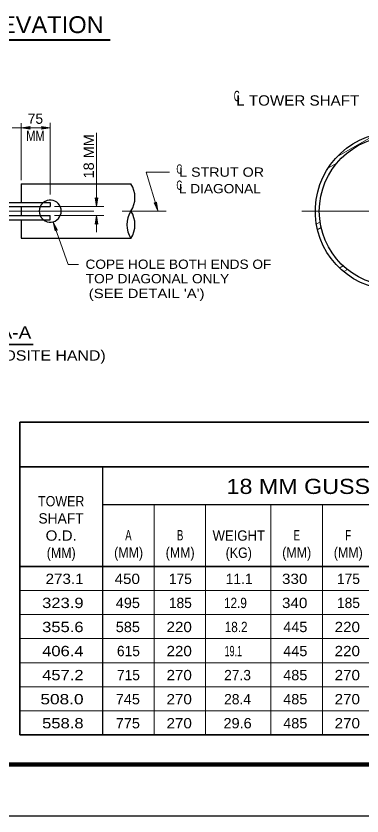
# Model space of a CAD drawing. Extents: x 312601.858 to 312602.699, y 144420.109 to 144420.704.
# Drawn here: x 312602.0136 to 312602.1142, y 144420.1095 to 144420.3423 of the extents above; entities that cross this region are included whole.
import ezdxf
from ezdxf.enums import TextEntityAlignment as Align

# ---------------------------------------------------------------- set-up
doc = ezdxf.new("R2010")
doc.units = 0
doc.header["$LTSCALE"] = 0.0012
doc.linetypes.add('DOT_DASHED', pattern=[7.7, 5, -1.2, 0.3, -1.2])
doc.linetypes.add('DOTTED', pattern=[1.5, 0.3, -1.2])
for name, color, linetype, lineweight in [('1', 7, 'Continuous', 25), ('2', 7, 'Continuous', 13), ('39', 7, 'Continuous', 13)]:
    doc.layers.add(name, color=color, linetype=linetype, lineweight=lineweight)

msp = doc.modelspace()

# ---------------------------------------------------------------- hatches: boundary and pattern name
at = {"layer": '39'}
for points in [[(312602.0174, 144420.3097), (312602.0177, 144420.3093), (312602.0151, 144420.3097), (312602.0177, 144420.3101)], [(312602.0174, 144420.3097), (312602.0177, 144420.3093), (312602.0151, 144420.3097), (312602.0177, 144420.3101)], [(312602.0212, 144420.3097), (312602.021, 144420.3101), (312602.0235, 144420.3097), (312602.021, 144420.3093)], [(312602.0212, 144420.3097), (312602.021, 144420.3101), (312602.0235, 144420.3097), (312602.021, 144420.3093)], [(312602.037, 144420.2891), (312602.0374, 144420.2894), (312602.037, 144420.2868), (312602.0366, 144420.2894)], [(312602.0541, 144420.2878), (312602.0544, 144420.2881), (312602.0548, 144420.2856), (312602.0537, 144420.2879)], [(312602.037, 144420.2819), (312602.0366, 144420.2817), (312602.037, 144420.2842), (312602.0374, 144420.2817)], [(312602.0252, 144420.2801), (312602.0249, 144420.2798), (312602.0244, 144420.2823), (312602.0256, 144420.28)]]:
    msp.add_hatch(color=256, dxfattribs=at).paths.add_polyline_path(points)

# ---------------------------------------------------------------- linework, layer by layer
at = {"layer": '1', "lineweight": 13}
for p, q in [((312602.0151, 144420.3111), (312602.0151, 144420.2945)), ((312602.0235, 144420.3112), (312602.0235, 144420.2903)), ((312602.037, 144420.3083), (312602.037, 144420.2868)), ((312602.1069, 144420.3013), (312602.1182, 144420.3078)), ((312602.1043, 144420.298), (312602.1069, 144420.2995)), ((312602.0514, 144420.2968), (312602.0582, 144420.2968)), ((312602.0514, 144420.2968), (312602.0548, 144420.2856)), ((312602.0247, 144420.2868), (312602.0391, 144420.2868)), ((312602.0247, 144420.2842), (312602.0391, 144420.2842)), ((312602.037, 144420.2842), (312602.037, 144420.2794)), ((312602.0444, 144420.2855), (312602.0572, 144420.2855)), ((312602.1009, 144420.2817), (312602.1021, 144420.2824)), ((312602.1012, 144420.2801), (312602.1023, 144420.2807)), ((312602.1076, 144420.2689), (312602.1087, 144420.2696)), ((312602.1089, 144420.2679), (312602.11, 144420.2685))]:
    msp.add_line(p, q, dxfattribs=at)
at = {"layer": '1'}
for p, q in [((312602.0151, 144420.2934), (312602.047, 144420.2934)), ((312602.0151, 144420.2934), (312602.0151, 144420.288)), ((312601.986, 144420.2868), (312602.0235, 144420.2868)), ((312601.9884, 144420.288), (312602.0235, 144420.288)), ((312602.0151, 144420.2868), (312602.0151, 144420.2842)), ((312602.0235, 144420.288), (312602.0235, 144420.2868)), ((312601.986, 144420.2842), (312602.0235, 144420.2842))]:
    msp.add_line(p, q, dxfattribs=at)
at = {"layer": '1', "linetype": 'DOT_DASHED', "lineweight": 13}
for p, q in [((312601.9362, 144420.2855), (312602.0468, 144420.2855)), ((312602.0967, 144420.2855), (312602.2188, 144420.2855))]:
    msp.add_line(p, q, dxfattribs=at)
at = {"layer": '1', "lineweight": 13}
for points in [[(312602.0124, 144420.3097), (312602.0151, 144420.3097), (312602.0235, 144420.3097)], [(312602.0317, 144420.27), (312602.0287, 144420.27), (312602.0244, 144420.2823)]]:
    msp.add_lwpolyline(points, dxfattribs=at)
at = {"layer": '1'}
for points in [[(312601.9884, 144420.283), (312602.0235, 144420.283), (312602.0235, 144420.2842)], [(312602.0151, 144420.283), (312602.0151, 144420.2776), (312602.047, 144420.2776)]]:
    msp.add_lwpolyline(points, dxfattribs=at)
msp.add_circle((312602.12356, 144420.2855), 0.02178, dxfattribs=at)
for centre, radius, start, end in [((312602.12356, 144420.2855), 0.02295, 3.25763, 2.95461), ((312602.0235, 144420.2855), 0.0032, 232.26694, 128.41806), ((312602.0235, 144420.2855), 0.0032, 156.57131, 203.32061)]:
    msp.add_arc(centre, radius, start, end, dxfattribs=at)
at = {"layer": '1', "linetype": 'DOTTED'}
for start, end in [(129.55967, 155.09523), (204.90477, 228.99091)]:
    msp.add_arc((312602.0235, 144420.2855), 0.0032, start, end, dxfattribs=at)
at = {"layer": '2', "lineweight": 40}
msp.add_line((312601.972, 144420.3353), (312602.0409, 144420.3353), dxfattribs=at)
at = {"layer": '2', "lineweight": 35}
for p, q in [((312601.982, 144420.2467), (312602.0185, 144420.2467)), ((312602.0147, 144420.2241), (312602.0147, 144420.1331)), ((312602.0147, 144420.2241), (312602.3284, 144420.2241)), ((312602.0147, 144420.2111), (312602.3287, 144420.2111)), ((312602.0147, 144420.1821), (312602.3287, 144420.1821)), ((312602.0147, 144420.1331), (312602.3287, 144420.1331))]:
    msp.add_line(p, q, dxfattribs=at)
at = {"layer": '2'}
for p, q in [((312602.0147, 144420.2241), (312602.0147, 144420.1331)), ((312602.0537, 144420.2001), (312602.0537, 144420.1331)), ((312602.0687, 144420.2001), (312602.0687, 144420.1331)), ((312602.0877, 144420.2001), (312602.0877, 144420.1331)), ((312602.1027, 144420.2001), (312602.1027, 144420.1331)), ((312602.0147, 144420.1751), (312602.3287, 144420.1751)), ((312602.0147, 144420.1681), (312602.3287, 144420.1681)), ((312602.0147, 144420.1611), (312602.3284, 144420.1611)), ((312602.0147, 144420.1541), (312602.3287, 144420.1541)), ((312602.0147, 144420.1471), (312602.3287, 144420.1471)), ((312602.0147, 144420.1401), (312602.3287, 144420.1401))]:
    msp.add_line(p, q, dxfattribs=at)
at = {"layer": '2', "lineweight": 25}
for p, q in [((312602.0387, 144420.2111), (312602.0387, 144420.1331)), ((312602.0387, 144420.2001), (312602.3287, 144420.2001))]:
    msp.add_line(p, q, dxfattribs=at)
for centre, start, end in [((312602.040877, 144420.28946), 327.02071, 32.97929), ((312602.053083, 144420.28154), 147.02071, 212.97929), ((312602.040877, 144420.28154), 327.02071, 32.97929)]:
    msp.add_arc(centre, 0.007275, start, end, dxfattribs=at)
at = {"layer": '39', "lineweight": 158}
msp.add_line((312601.9088, 144420.1245), (312602.6838, 144420.1245), dxfattribs=at)
at = {"layer": '39', "lineweight": 25}
msp.add_line((312601.8578, 144420.1095), (312602.6988, 144420.1095), dxfattribs=at)
at = {"layer": '39'}
for points in [[(312602.0174, 144420.3097), (312602.0177, 144420.3093), (312602.0151, 144420.3097), (312602.0177, 144420.3101)], [(312602.0174, 144420.3097), (312602.0177, 144420.3093), (312602.0151, 144420.3097), (312602.0177, 144420.3101)], [(312602.0212, 144420.3097), (312602.021, 144420.3101), (312602.0235, 144420.3097), (312602.021, 144420.3093)], [(312602.0212, 144420.3097), (312602.021, 144420.3101), (312602.0235, 144420.3097), (312602.021, 144420.3093)], [(312602.037, 144420.2891), (312602.0374, 144420.2894), (312602.037, 144420.2868), (312602.0366, 144420.2894)], [(312602.0541, 144420.2878), (312602.0544, 144420.2881), (312602.0548, 144420.2856), (312602.0537, 144420.2879)], [(312602.037, 144420.2819), (312602.0366, 144420.2817), (312602.037, 144420.2842), (312602.0374, 144420.2817)], [(312602.0252, 144420.2801), (312602.0249, 144420.2798), (312602.0244, 144420.2823), (312602.0256, 144420.28)]]:
    msp.add_lwpolyline(points, close=True, dxfattribs=at)

# ---------------------------------------------------------------- texts
at = {"layer": '2'}
for s, height, width, p in [('TOWER ELEVATION', 0.0049, 1.05, (312602.006, 144420.3373)), ('MM', 0.003, 0.8, (312602.0192, 144420.3059)), ('C', 0.0027, 0.65, (312602.06105, 144420.2964)), ('L STRUT OR', 0.0027, 1.15, (312602.07335, 144420.2955)), ('C', 0.0027, 0.65, (312602.06105, 144420.2917)), ('L DIAGONAL', 0.0027, 1.1, (312602.07285, 144420.2907)), ('COPE HOLE BOTH ENDS OF', 0.0027, 1.1, (312602.0608, 144420.2687)), ('TOP DIAGONAL ONLY', 0.0027, 1.1, (312602.0547, 144420.2645)), ("(SEE DETAIL 'A')", 0.0027, 1.2, (312602.05155, 144420.2602)), ('SECTION A-A', 0.0036, 1.15, (312602.0003, 144420.2484)), ('(SECTION D-D OPPOSITE HAND)', 0.003, 1.15, (312602.0035, 144420.242)), ('18 MM GUSSET PLATE', 0.0044, 1.15, (312602.11165, 144420.2032)), ('TOWER', 0.003, 0.9, (312602.0267, 144420.1996)), ('O.D.', 0.003, 1.1, (312602.0267, 144420.1896)), ('A', 0.003, 0.7, (312602.04625, 144420.1897)), ('B', 0.003, 0.7, (312602.0613, 144420.1897)), ('WEIGHT', 0.003, 0.95, (312602.07835, 144420.1896)), ('E', 0.003, 0.7, (312602.0952, 144420.1897)), ('F', 0.003, 0.7, (312602.11015, 144420.1897)), ('(MM)', 0.003, 0.9, (312602.0267, 144420.1846)), ('(MM)', 0.003, 0.9, (312602.0463, 144420.1847)), ('(MM)', 0.003, 0.9, (312602.0613, 144420.1847)), ('(KG)', 0.003, 0.9, (312602.07835, 144420.1846)), ('(MM)', 0.003, 0.9, (312602.0952, 144420.1847)), ('(MM)', 0.003, 0.9, (312602.1102, 144420.1847))]:
    msp.add_text(s, height=height, dxfattribs=dict(at, width=width)).set_placement(p, align=Align.CENTER)
for s, width, p in [('C', 0.6, (312602.0769, 144420.3175)), ('L TOWER SHAFT', 1.1, (312602.0776, 144420.3162))]:
    msp.add_text(s, height=0.003, dxfattribs=dict(at, width=width)).set_placement(p)
for s, p in [('75', (312602.0192, 144420.3109)), ('SHAFT', (312602.02665, 144420.1946))]:
    msp.add_text(s, height=0.003, dxfattribs=at).set_placement(p, align=Align.CENTER)
at = {"layer": '2', "width": 1.05}
msp.add_text('18 MM', height=0.003, rotation=90, dxfattribs=at).set_placement((312602.0362, 144420.30145), align=Align.CENTER)
at = {"layer": '2'}
for s, width, p in [('273.1', 1.1, (312602.0332, 144420.177)), ('450', 1.1, (312602.0496, 144420.177)), ('330', 1.1, (312602.0983, 144420.177)), ('323.9', 1.2, (312602.0332, 144420.17)), ('495', 1.05, (312602.0496, 144420.17)), ('12.9', 0.85, (312602.0807, 144420.17)), ('340', 1.1, (312602.0983, 144420.17)), ('355.6', 1.2, (312602.0332, 144420.163)), ('585', 1.05, (312602.0496, 144420.163)), ('220', 1.1, (312602.0647, 144420.163)), ('18.2', 0.85, (312602.0809, 144420.163)), ('445', 1.05, (312602.0983, 144420.163)), ('220', 1.1, (312602.1136, 144420.163)), ('406.4', 1.2, (312602.0332, 144420.156)), ('220', 1.1, (312602.0647, 144420.156)), ('19.1', 0.65, (312602.0793, 144420.156)), ('445', 1.05, (312602.0983, 144420.156)), ('220', 1.1, (312602.1136, 144420.156)), ('457.2', 1.2, (312602.0332, 144420.149)), ('270', 1.1, (312602.0647, 144420.149)), ('485', 1.05, (312602.0983, 144420.149)), ('270', 1.1, (312602.1136, 144420.149)), ('508.0', 1.25, (312602.0332, 144420.142)), ('745', 1.05, (312602.0496, 144420.142)), ('270', 1.1, (312602.0647, 144420.142)), ('485', 1.05, (312602.0983, 144420.142)), ('270', 1.1, (312602.1136, 144420.142)), ('558.8', 1.2, (312602.0332, 144420.135)), ('775', 1.05, (312602.0496, 144420.135)), ('270', 1.1, (312602.0647, 144420.135)), ('29.6', 1.05, (312602.0821, 144420.135)), ('485', 1.05, (312602.0983, 144420.135)), ('270', 1.1, (312602.1136, 144420.135))]:
    msp.add_text(s, height=0.003, dxfattribs=dict(at, width=width)).set_placement(p, align=Align.RIGHT)
for s, p in [('175', (312602.0647, 144420.177)), ('11.1', (312602.082357, 144420.177)), ('175', (312602.1136, 144420.177)), ('185', (312602.0647, 144420.17)), ('185', (312602.1136, 144420.17)), ('615', (312602.0496, 144420.156)), ('715', (312602.0496, 144420.149)), ('27.3', (312602.0819, 144420.149)), ('28.4', (312602.0819, 144420.142))]:
    msp.add_text(s, height=0.003, dxfattribs=at).set_placement(p, align=Align.RIGHT)

doc.saveas('drawing.dxf')
